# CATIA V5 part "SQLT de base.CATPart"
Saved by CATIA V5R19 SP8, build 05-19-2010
Part number: SQLT de base
Publications: "Point.A", "Point.B", "Point.C", "Point.D", "Point.E", "Point.F", "Point.G", "Point.H", "Point.I", "Point.J", "Point.K", "Point.L", "Point.M", "Point.N", "Point.O"
Bounding box of the stored display mesh (mm): x 0 to 0, y 0 to 1100, z 400 to 750
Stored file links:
  G:\EU_thinkMotion\CFAO_2010\MMS_groupe3\MMS_groupe3\A reprendre\fovide\fovide\SQLT de base.CATPart
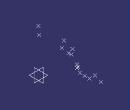
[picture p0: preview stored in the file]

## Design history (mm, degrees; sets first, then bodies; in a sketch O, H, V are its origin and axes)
Set1 "set de base"
  Point1 "Point.A": (0, 0, 750)
  Point2 "Point.B": (0, 450, 0), relative to Point1
  Point3 "Point.C": (0, 600, 700)
  Point4 "Point.D": (0, 1000, 500)
  Point5 "Point.E": (0, 1100, 450)
  Point6 "Point.F": (0, 900, 400)
  Point7 "Point.G": (0, 815, 400)
  Point8 "Point.H": (0, 730, 400)
  Point9 "Point.I": (0, 530, 600)
  Point10 "Point.J": (0, 680, 450)
  Point11 "Point.K": (0, 705, 475)
  Point12 "Point.L": (0, 680, 500)
  Point13 "Point.M": (0, 580, 605)
  Point14 "Point.N": (0, 410, 620)
  Point15 "Point.O": (0, 10, 620)
Body1 (main body)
